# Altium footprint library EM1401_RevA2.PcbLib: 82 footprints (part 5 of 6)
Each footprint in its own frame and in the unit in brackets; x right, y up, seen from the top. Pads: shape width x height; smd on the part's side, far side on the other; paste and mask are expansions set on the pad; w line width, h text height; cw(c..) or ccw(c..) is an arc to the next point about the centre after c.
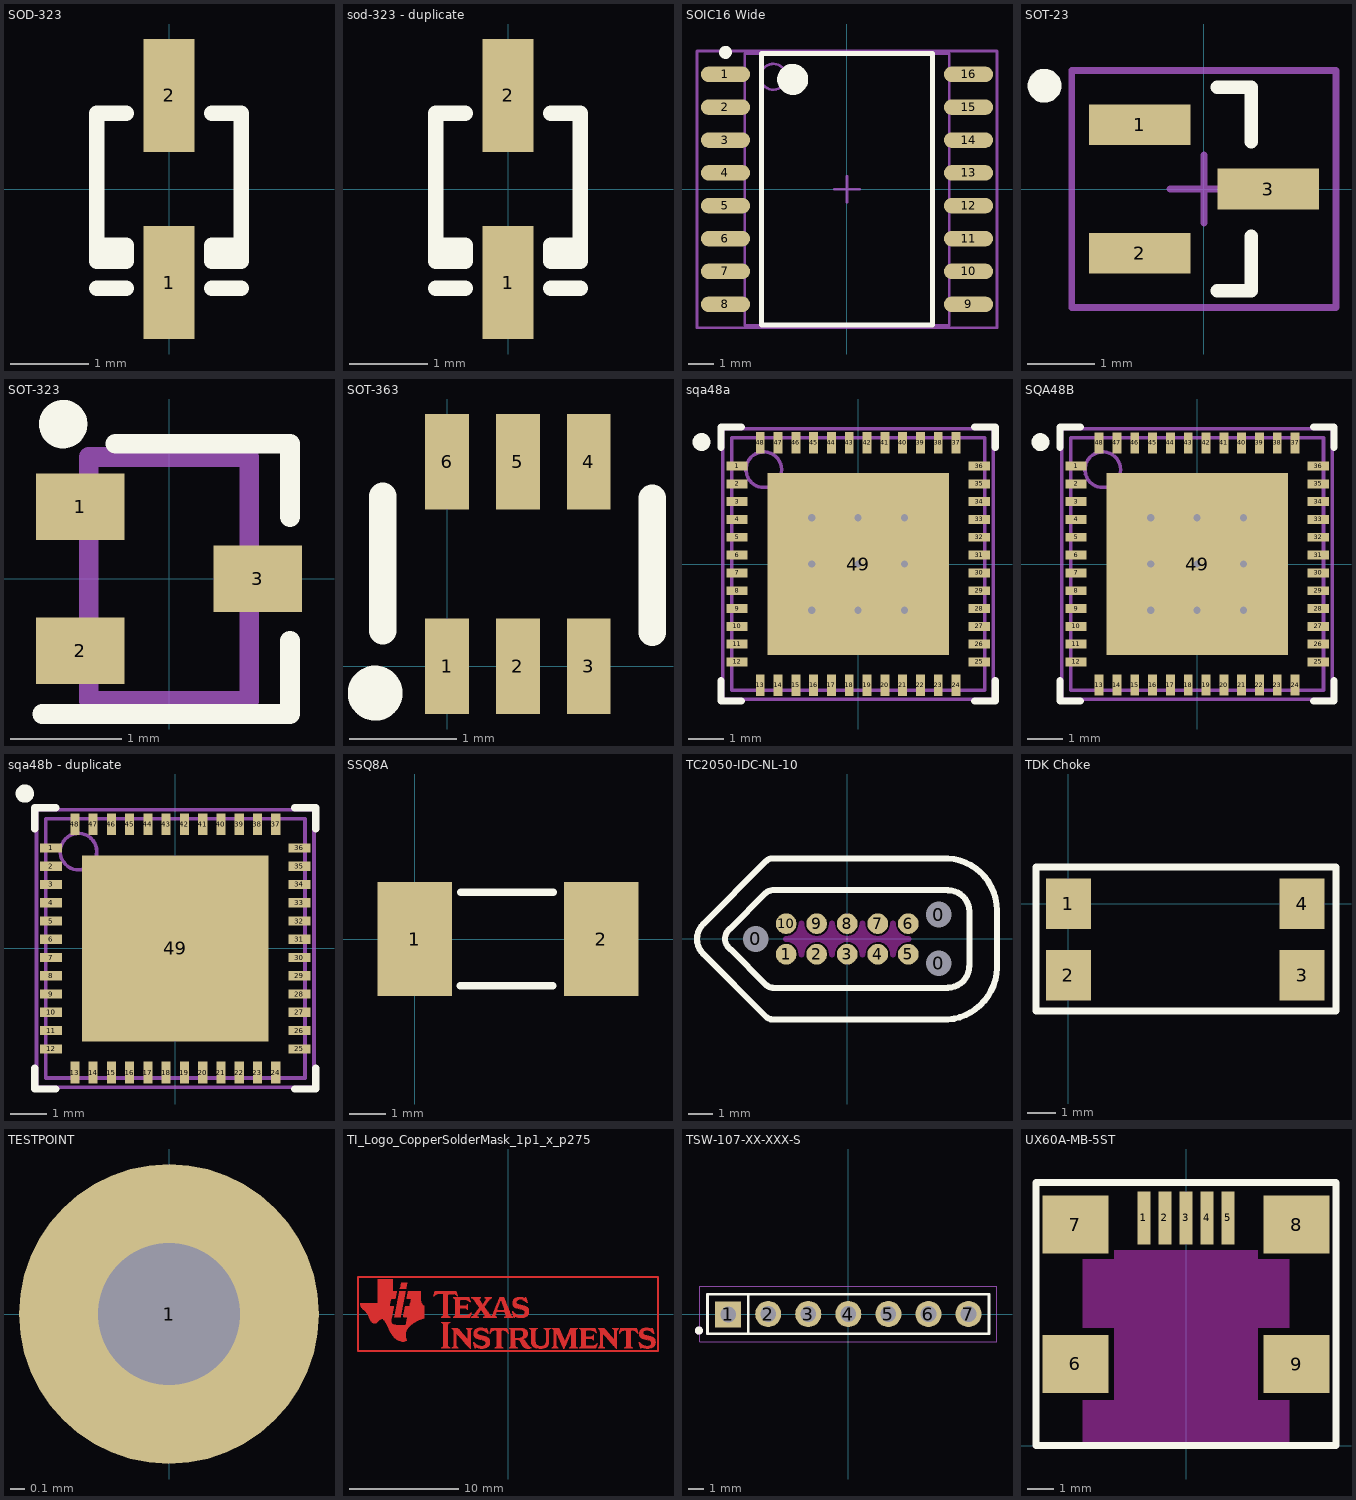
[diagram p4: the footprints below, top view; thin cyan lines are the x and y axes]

## SOD-323 [mm]
height 3.5
pads (2):
  rect 0.65x1.45 smd: 1(0,-1.2) 2(0,1.2)
Top Overlay:
  lines w0.2: -0.927,-0.725 -0.552,-0.725 -0.552,-0.926 -0.927,-0.926 -0.927,0.974 -0.552,0.974 ; -0.925,-1.275 -0.548,-1.275 ; 0.548,-1.275 0.925,-1.275 ; 0.548,0.974 0.925,0.974 0.925,-0.926 0.548,-0.926 0.548,-0.725 0.925,-0.725
Mechanical 5:
  text ".designator" at 0,-2 h1.02

## sod-323 - duplicate [mm]
pads (2):
  rect 0.65x1.45 smd: 1(0,-1.2) 2(0,1.2)
Top Overlay:
  lines w0.2: -0.927,-0.725 -0.552,-0.725 -0.552,-0.926 -0.927,-0.926 -0.927,0.974 -0.552,0.974 ; -0.925,-1.275 -0.548,-1.275 ; 0.548,-1.275 0.925,-1.275 ; 0.548,0.974 0.925,0.974 0.925,-0.926 0.548,-0.926 0.548,-0.725 0.925,-0.725
Mechanical 5:
  text ".designator" at 0,-2 h1.02

## SOIC16 Wide [mm]
pads (16):
  oval 1.9x0.6 smd: 1(-4.7,4.445) 2(-4.7,3.175) 3(-4.7,1.905) 4(-4.7,0.635) 5(-4.7,-0.635) 6(-4.7,-1.905) 7(-4.7,-3.175) 8(-4.7,-4.445) 9(4.7,-4.445) 10(4.7,-3.175) 11(4.7,-1.905) 12(4.7,-0.635) 13(4.7,0.635) 14(4.7,1.905) 15(4.7,3.175) 16(4.7,4.445)
Top Overlay:
  circle w0.6: c-2.1,4.25 r0.3
  circle w0.25: c-4.7,5.295 r0.125
  lines w0.2: -3.3,-5.25 3.3,-5.25 3.3,5.25 -3.3,5.25 -3.3,-5.25
Mechanical 5:
  text ".Designator" at -1.524,-0.508 h1.02
Mechanical 13:
  circle w0.1: c-2.85,4.35 r0.5
  lines w0.1: -3.95,-5.25 3.95,-5.25 3.95,5.25 -3.95,5.25 -3.95,-5.25
Mechanical 15:
  lines w0.1: -0.5,0 0.5,0 ; 0,-0.5 0,0.5 ; -5.8,-5.35 5.8,-5.35 5.8,5.35 -5.8,5.35 -5.8,-5.35
3D body: height 2.65, standoff 0, extent -3.95,-5.25 3.95,5.25

## SOT-23 [mm] "SOT23, 3-Leads, Body 2.9x1.3mm, Pitch 0.95mm, Lead Span 2.5mm, IPC Medium Density"
height 1.1
pads (3):
  rect 1.5x0.6 smd: 1(-0.95,0.95) 2(-0.95,-0.95) 3(0.95,0)
Top Overlay:
  circle w0.25: c-2.354,1.524 r0.125
  lines w0.2: 0.2,-1.5 0.7,-1.5 0.7,-0.7 ; 0.2,1.5 0.7,1.5 0.7,0.7
Mechanical 5:
  text ".Designator" at -1.524,-0.508 h1.02
Mechanical 15:
  lines w0.1: -0.5,0 0.5,0 ; 0,-0.5 0,0.5 ; -1.95,-1.75 -1.95,1.75 1.95,1.75 1.95,-1.75 -1.95,-1.75
3D body: height 1, standoff 0, extent -1.16,-1.45 1.21,1.45

## SOT-323 [mm] "SC-70-3 and SOT-323 footrpint"
height 1.1
pads (3):
  rect 0.8x0.6 smd: 1(-0.8,0.65) 2(-0.8,-0.65) 3(0.8,0)
Top Overlay:
  circle w0.254: c-0.955,1.397 r0.092
  lines w0.178: -1.143,-1.219 1.092,-1.219 1.092,-0.559 ; -0.483,1.219 1.092,1.219 1.092,0.559
Mechanical 5:
  text ".Designator" at -1.524,-0.508 h1.02
Mechanical 13:
  lines w0.178: -0.725,-1.1 0,-1.1 0.725,-1.1 0.725,0 0.725,1.1 0,1.1 -0.725,1.1 -0.725,0 -0.725,-1.1
3D body: height 1.1, standoff 0, extent -0.724,-1.099 0.724,1.099

## SOT-363 [mil] "SOT-363 FOOTPRINT"
height 137.8
pads (6):
  rect 16x35 smd: 1(0,0) 2(26,0) 3(52,0) 4(52,75) 5(26,75) 6(0,75)
Top Overlay:
  circle w11.81: c-26.35,-9.84 r4.16
  lines w10: -23.6,13 -23.6,62.3 ; 75.2,12.4 75.2,61.7

## sqa48a [mm] "QFN, 48-Leads, Body 7x7mm, Pitch 0.5mm, NSC Recommended"
height 0.8
pads (49):
  rect 0.6x0.25 smd paste-0.125 mask+0.051: 1(-3.4,2.75) 2(-3.4,2.25) 3(-3.4,1.75) 4(-3.4,1.25) 5(-3.4,0.75) 6(-3.4,0.25) 7(-3.4,-0.25) 8(-3.4,-0.75) 9(-3.4,-1.25) 10(-3.4,-1.75) 11(-3.4,-2.25) 12(-3.4,-2.75) 25(3.4,-2.75) 26(3.4,-2.25) 27(3.4,-1.75) 28(3.4,-1.25) 29(3.4,-0.75) 30(3.4,-0.25) 31(3.4,0.25) 32(3.4,0.75) 33(3.4,1.25) 34(3.4,1.75) 35(3.4,2.25) 36(3.4,2.75)
  rect 0.25x0.6 smd paste-0.125 mask+0.051: 13(-2.75,-3.4) 14(-2.25,-3.4) 15(-1.75,-3.4) 16(-1.25,-3.4) 17(-0.75,-3.4) 18(-0.25,-3.4) 19(0.25,-3.4) 20(0.75,-3.4) 21(1.25,-3.4) 22(1.75,-3.4) 23(2.25,-3.4) 24(2.75,-3.4) 37(2.75,3.4) 38(2.25,3.4) 39(1.75,3.4) 40(1.25,3.4) 41(0.75,3.4) 42(0.25,3.4) 43(-0.25,3.4) 44(-0.75,3.4) 45(-1.25,3.4) 46(-1.75,3.4) 47(-2.25,3.4) 48(-2.75,3.4)
  rect 5.1x5.1 smd paste-2.55 mask+0.051: 49(0,0)
via 1.3,1.3 diameter 0.635 hole 0.203
via 1.3,0 diameter 0.635 hole 0.203
via 0,1.3 diameter 0.635 hole 0.203
via 0,0 diameter 0.635 hole 0.203
via 1.3,-1.3 diameter 0.635 hole 0.203
via 0,-1.3 diameter 0.635 hole 0.203
via -1.3,1.3 diameter 0.635 hole 0.203
via -1.3,0 diameter 0.635 hole 0.203
via -1.3,-1.3 diameter 0.635 hole 0.203
Top Overlay:
  circle w0.25: c-4.4,3.425 r0.125
  lines w0.2: -3.85,-3.275 -3.85,-3.85 -3.275,-3.85 ; -3.85,3.275 -3.85,3.85 -3.275,3.85 ; 3.275,-3.85 3.85,-3.85 3.85,-3.275 ; 3.275,3.85 3.85,3.85 3.85,3.275
Top Paste:
  region: 3.9,2.875 3.2,2.875 3.2,2.625 3.9,2.625
  region: 3.9,2.375 3.2,2.375 3.2,2.125 3.9,2.125
  region: 2.625,3.9 2.625,3.2 2.875,3.2 2.875,3.9
  rectangle: 1.4,1.4 2.5,2.5
  region: 3.9,1.875 3.2,1.875 3.2,1.625 3.9,1.625
  region: 3.9,0.875 3.2,0.875 3.2,0.625 3.9,0.625
  region: 3.896,1.375 3.196,1.375 3.196,1.125 3.896,1.125
  region: 3.9,-0.125 3.2,-0.125 3.2,-0.375 3.9,-0.375
  region: 3.9,0.375 3.2,0.375 3.2,0.125 3.9,0.125
  region: 2.125,3.9 2.125,3.2 2.375,3.2 2.375,3.9
  region: 1.625,3.9 1.625,3.2 1.875,3.2 1.875,3.9
  region: 1.125,3.9 1.125,3.2 1.375,3.2 1.375,3.9
  region: 0.625,3.9 0.625,3.2 0.875,3.2 0.875,3.9
  region: 0.125,3.9 0.125,3.2 0.375,3.2 0.375,3.9
  region: -0.375,3.9 -0.375,3.2 -0.125,3.2 -0.125,3.9
  rectangle: 1.4,0.1 2.5,1.2
  rectangle: 0.1,1.4 1.2,2.5
  rectangle: 0.1,0.1 1.2,1.2
  region: 3.9,-0.625 3.2,-0.625 3.2,-0.875 3.9,-0.875
  region: 3.896,-1.125 3.196,-1.125 3.196,-1.375 3.896,-1.375
  region: 1.4,-0.1 1.4,-1.2 2.5,-1.2 2.5,-0.1
  region: 3.9,-1.625 3.2,-1.625 3.2,-1.875 3.9,-1.875
  region: 3.9,-2.125 3.2,-2.125 3.2,-2.375 3.9,-2.375
  region: 3.9,-2.625 3.2,-2.625 3.2,-2.875 3.9,-2.875
  region: 2.875,-3.9 2.875,-3.2 2.625,-3.2 2.625,-3.9
  region: 1.4,-1.4 1.4,-2.5 2.5,-2.5 2.5,-1.4
  region: 0.1,-0.1 0.1,-1.2 1.2,-1.2 1.2,-0.1
  region: 0.1,-1.4 0.1,-2.5 1.2,-2.5 1.2,-1.4
  region: 1.371,-3.9 1.371,-3.2 1.121,-3.2 1.121,-3.9
  region: 0.871,-3.9 0.871,-3.2 0.621,-3.2 0.621,-3.9
  region: 2.375,-3.9 2.375,-3.2 2.125,-3.2 2.125,-3.9
  region: 1.875,-3.9 1.875,-3.2 1.625,-3.2 1.625,-3.9
  region: 0.375,-3.9 0.375,-3.2 0.125,-3.2 0.125,-3.9
  region: -0.125,-3.9 -0.125,-3.2 -0.375,-3.2 -0.375,-3.9
  region: -0.875,3.9 -0.875,3.2 -0.625,3.2 -0.625,3.9
  region: -1.375,3.9 -1.375,3.2 -1.125,3.2 -1.125,3.9
  region: -1.875,3.9 -1.875,3.2 -1.625,3.2 -1.625,3.9
  region: -0.1,2.5 -1.2,2.5 -1.2,1.4 -0.1,1.4
  region: -0.1,1.2 -1.2,1.2 -1.2,0.1 -0.1,0.1
  region: -1.4,1.2 -2.5,1.2 -2.5,0.1 -1.4,0.1
  region: -1.4,2.5 -2.5,2.5 -2.5,1.4 -1.4,1.4
  region: -2.375,3.9 -2.375,3.2 -2.125,3.2 -2.125,3.9
  region: -2.875,3.9 -2.875,3.2 -2.625,3.2 -2.625,3.9
  rectangle: -3.9,2.625 -3.2,2.875
  rectangle: -3.9,1.625 -3.2,1.875
  rectangle: -3.9,1.125 -3.2,1.375
  rectangle: -3.9,2.125 -3.2,2.375
  rectangle: -3.9,0.125 -3.2,0.375
  rectangle: -3.9,0.625 -3.2,0.875
  region: -1.2,-0.1 -1.2,-1.2 -0.1,-1.2 -0.1,-0.1
  region: -1.2,-1.4 -1.2,-2.5 -0.1,-2.5 -0.1,-1.4
  region: -2.5,-1.4 -2.5,-2.5 -1.4,-2.5 -1.4,-1.4
  region: -2.5,-0.1 -2.5,-1.2 -1.4,-1.2 -1.4,-0.1
  region: -1.129,-3.9 -1.129,-3.2 -1.379,-3.2 -1.379,-3.9
  region: -0.625,-3.9 -0.625,-3.2 -0.875,-3.2 -0.875,-3.9
  region: -1.629,-3.9 -1.629,-3.2 -1.879,-3.2 -1.879,-3.9
  region: -2.125,-3.9 -2.125,-3.2 -2.375,-3.2 -2.375,-3.9
  rectangle: -3.9,-0.875 -3.2,-0.625
  rectangle: -3.9,-0.375 -3.2,-0.125
  rectangle: -3.9,-1.375 -3.2,-1.125
  rectangle: -3.9,-2.375 -3.2,-2.125
  region: -2.625,-3.9 -2.625,-3.2 -2.875,-3.2 -2.875,-3.9
  rectangle: -3.9,-2.875 -3.2,-2.625
  rectangle: -3.9,-1.875 -3.2,-1.625
Mechanical 13:
  circle w0.1: c-2.65,2.65 r0.5
  lines w0.1: -3.55,-3.55 3.55,-3.55 3.55,3.55 -3.55,3.55 -3.55,-3.55
Mechanical 15:
  lines w0.1: -0.5,0 0.5,0 ; 0,-0.5 0,0.5 ; -3.8,-3.8 3.8,-3.8 3.8,3.8 -3.8,3.8 -3.8,-3.8
3D body: height 0.8, standoff 0, extent -3.55,-3.55 3.55,3.55

## SQA48B [mm] "QFN, 48-Leads, Body 7x7mm, Pitch 0.5mm, NSC Recommended"
height 0.8
pads (49):
  rect 0.6x0.25 smd paste-0.125 mask+0.051: 1(-3.4,2.75) 2(-3.4,2.25) 3(-3.4,1.75) 4(-3.4,1.25) 5(-3.4,0.75) 6(-3.4,0.25) 7(-3.4,-0.25) 8(-3.4,-0.75) 9(-3.4,-1.25) 10(-3.4,-1.75) 11(-3.4,-2.25) 12(-3.4,-2.75) 25(3.4,-2.75) 26(3.4,-2.25) 27(3.4,-1.75) 28(3.4,-1.25) 29(3.4,-0.75) 30(3.4,-0.25) 31(3.4,0.25) 32(3.4,0.75) 33(3.4,1.25) 34(3.4,1.75) 35(3.4,2.25) 36(3.4,2.75)
  rect 0.25x0.6 smd paste-0.125 mask+0.051: 13(-2.75,-3.4) 14(-2.25,-3.4) 15(-1.75,-3.4) 16(-1.25,-3.4) 17(-0.75,-3.4) 18(-0.25,-3.4) 19(0.25,-3.4) 20(0.75,-3.4) 21(1.25,-3.4) 22(1.75,-3.4) 23(2.25,-3.4) 24(2.75,-3.4) 37(2.75,3.4) 38(2.25,3.4) 39(1.75,3.4) 40(1.25,3.4) 41(0.75,3.4) 42(0.25,3.4) 43(-0.25,3.4) 44(-0.75,3.4) 45(-1.25,3.4) 46(-1.75,3.4) 47(-2.25,3.4) 48(-2.75,3.4)
  rect 5.1x5.1 smd paste-2.55 mask+0.051: 49(0,0)
via -1.3,1.3 diameter 0.635 hole 0.203
via 0,0 diameter 0.635 hole 0.203
via 0,1.3 diameter 0.635 hole 0.203
via 1.3,1.3 diameter 0.635 hole 0.203
via 1.3,0 diameter 0.635 hole 0.203
via -1.3,0 diameter 0.635 hole 0.203
via -1.3,-1.3 diameter 0.635 hole 0.203
via 0,-1.3 diameter 0.635 hole 0.203
via 1.3,-1.3 diameter 0.635 hole 0.203
Top Overlay:
  circle w0.25: c-4.4,3.425 r0.125
  lines w0.2: -3.85,-3.275 -3.85,-3.85 -3.275,-3.85 ; -3.85,3.275 -3.85,3.85 -3.275,3.85 ; 3.275,-3.85 3.85,-3.85 3.85,-3.275 ; 3.275,3.85 3.85,3.85 3.85,3.275
Top Paste:
  region: -2.377,3.9 -2.377,3.2 -2.127,3.2 -2.127,3.9
  region: -2.877,3.9 -2.877,3.2 -2.627,3.2 -2.627,3.9
  region: -1.877,3.9 -1.877,3.2 -1.627,3.2 -1.627,3.9
  region: -0.875,3.901 -0.875,3.201 -0.625,3.201 -0.625,3.901
  region: -1.375,3.898 -1.375,3.198 -1.125,3.198 -1.125,3.898
  region: 0.123,3.9 0.123,3.2 0.373,3.2 0.373,3.9
  region: -0.377,3.9 -0.377,3.2 -0.127,3.2 -0.127,3.9
  rectangle: -3.902,2.125 -3.202,2.375
  rectangle: -3.902,2.625 -3.202,2.875
  rectangle: -3.9,1.623 -3.2,1.873
  rectangle: -3.902,0.125 -3.202,0.375
  rectangle: -3.902,-0.375 -3.202,-0.125
  rectangle: -3.9,1.123 -3.2,1.373
  rectangle: -3.902,0.625 -3.202,0.875
  region: -1.4,2.5 -2.5,2.5 -2.5,1.4 -1.4,1.4
  region: -0.1,2.5 -1.2,2.5 -1.2,1.4 -0.1,1.4
  region: -1.4,1.2 -2.5,1.2 -2.5,0.1 -1.4,0.1
  region: -0.1,1.2 -1.2,1.2 -1.2,0.1 -0.1,0.1
  region: 0.623,3.9 0.623,3.2 0.873,3.2 0.873,3.9
  region: 1.125,3.898 1.125,3.198 1.375,3.198 1.375,3.898
  rectangle: 1.4,1.4 2.5,2.5
  region: 2.123,3.9 2.123,3.2 2.373,3.2 2.373,3.9
  region: 2.623,3.9 2.623,3.2 2.873,3.2 2.873,3.9
  region: 1.625,3.898 1.625,3.198 1.875,3.198 1.875,3.898
  region: 3.898,2.875 3.198,2.875 3.198,2.625 3.898,2.625
  rectangle: 0.1,1.4 1.2,2.5
  rectangle: 0.1,0.1 1.2,1.2
  rectangle: 1.4,0.1 2.5,1.2
  region: 3.898,2.375 3.198,2.375 3.198,2.125 3.898,2.125
  region: 3.898,1.875 3.198,1.875 3.198,1.625 3.898,1.625
  region: 3.901,1.372 3.201,1.372 3.201,1.122 3.901,1.122
  region: 3.9,0.875 3.2,0.875 3.2,0.625 3.9,0.625
  region: 3.898,0.375 3.198,0.375 3.198,0.125 3.898,0.125
  region: 3.898,-0.125 3.198,-0.125 3.198,-0.375 3.898,-0.375
  rectangle: -3.9,-0.877 -3.2,-0.627
  rectangle: -3.9,-1.377 -3.2,-1.127
  rectangle: -3.902,-1.875 -3.202,-1.625
  region: -2.5,-0.1 -2.5,-1.2 -1.4,-1.2 -1.4,-0.1
  region: -1.2,-0.1 -1.2,-1.2 -0.1,-1.2 -0.1,-0.1
  region: -2.5,-1.4 -2.5,-2.5 -1.4,-2.5 -1.4,-1.4
  region: -1.2,-1.4 -1.2,-2.5 -0.1,-2.5 -0.1,-1.4
  rectangle: -3.902,-2.375 -3.202,-2.125
  rectangle: -3.902,-2.875 -3.202,-2.625
  region: -2.127,-3.9 -2.127,-3.2 -2.377,-3.2 -2.377,-3.9
  region: -2.627,-3.9 -2.627,-3.2 -2.877,-3.2 -2.877,-3.9
  region: -0.127,-3.9 -0.127,-3.2 -0.377,-3.2 -0.377,-3.9
  region: -1.123,-3.903 -1.123,-3.203 -1.373,-3.203 -1.373,-3.903
  region: -1.623,-3.903 -1.623,-3.203 -1.873,-3.203 -1.873,-3.903
  region: 0.373,-3.9 0.373,-3.2 0.123,-3.2 0.123,-3.9
  region: -0.627,-3.9 -0.627,-3.2 -0.877,-3.2 -0.877,-3.9
  region: 0.1,-0.1 0.1,-1.2 1.2,-1.2 1.2,-0.1
  region: 1.4,-0.1 1.4,-1.2 2.5,-1.2 2.5,-0.1
  region: 1.4,-1.4 1.4,-2.5 2.5,-2.5 2.5,-1.4
  region: 0.1,-1.4 0.1,-2.5 1.2,-2.5 1.2,-1.4
  region: 3.898,-0.625 3.198,-0.625 3.198,-0.875 3.898,-0.875
  region: 3.901,-1.128 3.201,-1.128 3.201,-1.378 3.901,-1.378
  region: 3.9,-1.625 3.2,-1.625 3.2,-1.875 3.9,-1.875
  region: 3.898,-2.125 3.198,-2.125 3.198,-2.375 3.898,-2.375
  region: 1.376,-3.903 1.376,-3.203 1.126,-3.203 1.126,-3.903
  region: 0.876,-3.903 0.876,-3.203 0.626,-3.203 0.626,-3.903
  region: 1.873,-3.9 1.873,-3.2 1.623,-3.2 1.623,-3.9
  region: 3.898,-2.625 3.198,-2.625 3.198,-2.875 3.898,-2.875
  region: 2.873,-3.9 2.873,-3.2 2.623,-3.2 2.623,-3.9
  region: 2.373,-3.9 2.373,-3.2 2.123,-3.2 2.123,-3.9
Mechanical 13:
  circle w0.1: c-2.65,2.65 r0.5
  lines w0.1: -3.55,-3.55 -3.55,3.55 3.55,3.55 3.55,-3.55 -3.55,-3.55
Mechanical 15:
  lines w0.1: -0.5,0 0.5,0 ; 0,-0.5 0,0.5 ; -3.8,-3.8 -3.8,3.8 3.8,3.8 3.8,-3.8 -3.8,-3.8
3D body: height 0.8, standoff 0, extent -3.55,-3.55 3.55,3.55

## sqa48b - duplicate [mm]
pads (49):
  rect 0.6x0.25 smd paste-0.125 mask+0.051: 1(-3.4,2.75) 2(-3.4,2.25) 3(-3.4,1.75) 4(-3.4,1.25) 5(-3.4,0.75) 6(-3.4,0.25) 7(-3.4,-0.25) 8(-3.4,-0.75) 9(-3.4,-1.25) 10(-3.4,-1.75) 11(-3.4,-2.25) 12(-3.4,-2.75) 25(3.4,-2.75) 26(3.4,-2.25) 27(3.4,-1.75) 28(3.4,-1.25) 29(3.4,-0.75) 30(3.4,-0.25) 31(3.4,0.25) 32(3.4,0.75) 33(3.4,1.25) 34(3.4,1.75) 35(3.4,2.25) 36(3.4,2.75)
  rect 0.25x0.6 smd paste-0.125 mask+0.051: 13(-2.75,-3.4) 14(-2.25,-3.4) 15(-1.75,-3.4) 16(-1.25,-3.4) 17(-0.75,-3.4) 18(-0.25,-3.4) 19(0.25,-3.4) 20(0.75,-3.4) 21(1.25,-3.4) 22(1.75,-3.4) 23(2.25,-3.4) 24(2.75,-3.4) 37(2.75,3.4) 38(2.25,3.4) 39(1.75,3.4) 40(1.25,3.4) 41(0.75,3.4) 42(0.25,3.4) 43(-0.25,3.4) 44(-0.75,3.4) 45(-1.25,3.4) 46(-1.75,3.4) 47(-2.25,3.4) 48(-2.75,3.4)
  rect 5.1x5.1 smd paste-2.55 mask+0.051: 49(0,0)
Top Overlay:
  circle w0.25: c-4.12,4.24 r0.125
  lines w0.2: -3.85,-3.275 -3.85,-3.85 -3.275,-3.85 ; -3.85,3.275 -3.85,3.85 -3.275,3.85 ; 3.275,-3.85 3.85,-3.85 3.85,-3.275 ; 3.275,3.85 3.85,3.85 3.85,3.275
Top Paste:
  region: 3.898,-2.625 3.198,-2.625 3.198,-2.875 3.898,-2.875
  region: 3.9,-1.625 3.2,-1.625 3.2,-1.875 3.9,-1.875
  region: 3.898,-2.125 3.198,-2.125 3.198,-2.375 3.898,-2.375
  region: 3.9,-1.125 3.2,-1.125 3.2,-1.375 3.9,-1.375
  region: 3.898,-0.625 3.198,-0.625 3.198,-0.875 3.898,-0.875
  region: 3.898,0.375 3.198,0.375 3.198,0.125 3.898,0.125
  region: 3.898,-0.125 3.198,-0.125 3.198,-0.375 3.898,-0.375
  region: 2.374,-3.9 2.374,-3.2 2.124,-3.2 2.124,-3.9
  region: 2.874,-3.9 2.874,-3.2 2.624,-3.2 2.624,-3.9
  region: 1.874,-3.9 1.874,-3.2 1.624,-3.2 1.624,-3.9
  region: 1.375,-3.9 1.375,-3.2 1.125,-3.2 1.125,-3.9
  region: 0.875,-3.9 0.875,-3.2 0.625,-3.2 0.625,-3.9
  region: 0.374,-3.9 0.374,-3.2 0.124,-3.2 0.124,-3.9
  region: -0.126,-3.9 -0.126,-3.2 -0.376,-3.2 -0.376,-3.9
  region: 1.4,-0.1 1.4,-1.2 2.5,-1.2 2.5,-0.1
  region: 1.4,-1.4 1.4,-2.5 2.5,-2.5 2.5,-1.4
  region: 0.1,-0.1 0.1,-1.2 1.2,-1.2 1.2,-0.1
  region: 0.1,-1.4 0.1,-2.5 1.2,-2.5 1.2,-1.4
  region: 3.9,0.875 3.2,0.875 3.2,0.625 3.9,0.625
  region: 3.9,1.375 3.2,1.375 3.2,1.125 3.9,1.125
  region: 3.898,1.875 3.198,1.875 3.198,1.625 3.898,1.625
  rectangle: 1.4,0.1 2.5,1.2
  region: 3.898,2.875 3.198,2.875 3.198,2.625 3.898,2.625
  region: 3.898,2.375 3.198,2.375 3.198,2.125 3.898,2.125
  region: 2.623,3.9 2.623,3.2 2.873,3.2 2.873,3.9
  rectangle: 1.4,1.4 2.5,2.5
  rectangle: 0.1,0.1 1.2,1.2
  rectangle: 0.1,1.4 1.2,2.5
  region: 2.123,3.9 2.123,3.2 2.373,3.2 2.373,3.9
  region: 1.624,3.901 1.624,3.201 1.874,3.201 1.874,3.901
  region: 1.124,3.901 1.124,3.201 1.374,3.201 1.374,3.901
  region: 0.624,3.9 0.624,3.2 0.874,3.2 0.874,3.9
  region: 0.124,3.9 0.124,3.2 0.374,3.2 0.374,3.9
  region: -0.376,3.9 -0.376,3.2 -0.126,3.2 -0.126,3.9
  region: -1.125,-3.9 -1.125,-3.2 -1.375,-3.2 -1.375,-3.9
  region: -0.626,-3.9 -0.626,-3.2 -0.876,-3.2 -0.876,-3.9
  region: -1.625,-3.9 -1.625,-3.2 -1.875,-3.2 -1.875,-3.9
  region: -2.626,-3.9 -2.626,-3.2 -2.876,-3.2 -2.876,-3.9
  region: -2.126,-3.9 -2.126,-3.2 -2.376,-3.2 -2.376,-3.9
  region: -1.2,-1.4 -1.2,-2.5 -0.1,-2.5 -0.1,-1.4
  region: -1.2,-0.1 -1.2,-1.2 -0.1,-1.2 -0.1,-0.1
  region: -2.5,-0.1 -2.5,-1.2 -1.4,-1.2 -1.4,-0.1
  region: -2.5,-1.4 -2.5,-2.5 -1.4,-2.5 -1.4,-1.4
  rectangle: -3.901,-2.375 -3.201,-2.125
  rectangle: -3.901,-1.875 -3.201,-1.625
  rectangle: -3.901,-2.875 -3.201,-2.625
  rectangle: -3.9,-0.874 -3.2,-0.624
  rectangle: -3.9,-1.374 -3.2,-1.124
  rectangle: -3.901,-0.375 -3.201,-0.125
  rectangle: -3.901,0.625 -3.201,0.875
  rectangle: -3.901,0.125 -3.201,0.375
  region: -0.1,1.2 -1.2,1.2 -1.2,0.1 -0.1,0.1
  region: -0.1,2.5 -1.2,2.5 -1.2,1.4 -0.1,1.4
  region: -1.4,1.2 -2.5,1.2 -2.5,0.1 -1.4,0.1
  region: -1.4,2.5 -2.5,2.5 -2.5,1.4 -1.4,1.4
  region: -0.875,3.898 -0.875,3.198 -0.625,3.198 -0.625,3.898
  region: -1.375,3.901 -1.375,3.201 -1.125,3.201 -1.125,3.901
  region: -1.876,3.9 -1.876,3.2 -1.626,3.2 -1.626,3.9
  region: -2.376,3.9 -2.376,3.2 -2.126,3.2 -2.126,3.9
  rectangle: -3.9,1.626 -3.2,1.876
  rectangle: -3.9,1.126 -3.2,1.376
  rectangle: -3.901,2.625 -3.201,2.875
  region: -2.876,3.9 -2.876,3.2 -2.626,3.2 -2.626,3.9
  rectangle: -3.901,2.125 -3.201,2.375
Mechanical 13:
  circle w0.1: c-2.65,2.65 r0.5
  lines w0.1: -3.55,-3.55 3.55,-3.55 3.55,3.55 -3.55,3.55 -3.55,-3.55
Mechanical 15:
  lines w0.1: -0.5,0 0.5,0 ; 0,-0.5 0,0.5 ; -3.8,-3.8 3.8,-3.8 3.8,3.8 -3.8,3.8 -3.8,-3.8
3D body: height 0.8, standoff 0, extent -3.55,-3.55 3.55,3.55

## SSQ8A [mm] "Bel Fuse SMT Quick Acting Fuse"
height 2.54
pads (2):
  rect 2.032x3.1 smd: 1(0,0) 2(5.08,0)
Top Overlay:
  lines w0.203: 1.24,-1.27 3.765,-1.27 ; 1.25,1.27 3.775,1.27
Mechanical 5:
  text ".designator" at 1.495,-0.42 h1.02
3D body: height 2.54, standoff 0, extent 0,-1.27 5.08,1.27

## TC2050-IDC-NL-10 [mil]
pads (13):
  round 39 hole 42 unplated: 0(-150,0) 0(150,-40) 0(150,40)
  round 34 smd: 1(-100,-25) 2(-50,-25) 3(0,-25) 4(50,-25) 5(100,-25) 6(100,25) 7(50,25) 8(0,25) 9(-50,25) 10(-100,25)
Top Overlay:
  lines w10: -236.02,24.32 -132.42,127.92 cw(c-120.91,113.83) -120,132 165,132 cw(c160,47) 245.15,47 ; -235.97,-24.19 -132.37,-127.78 ccw(c-120.71,-113.82) -120,-132 165,-132 ccw(c158,-45) 245.25,-47.35 ; -235.6,-24.55 cw(c-211.74,0.03) -235.57,24.65 ; -133.15,75.43 -191.54,17.04 ccw(c-178.99,0.19) -190.97,-17.07 -132.58,-75.46 ; -132.42,75.92 cw(c-120.91,61.83) -120,80 165.34,80 ; -132.37,-75.78 ccw(c-120.71,-61.82) -120,-80 165,-80 ; 165,-79.66 ccw(c165,-45) 199.66,-45 ; 165.34,79.66 cw(c165.34,45) 200,45 200,-45 ; 245,-47.34 245,45
Keep-Out Layer:
  region: -6.61,0 -25,18.38 -43.38,0 -25,-18.38
  region: -56.61,0 -75,18.38 -93.38,0 -75,-18.38
  region: 43.39,0 25,18.38 6.62,0 25,-18.38
  region: 93.39,0 75,18.38 56.62,0 75,-18.38
  lines w10: -100,-0.02 ccw(c-100,25) -74.98,25 ; -100,0.08 cw(c-100,-25) -74.92,-25 cw(c-50,-25) -50,-0.08 ; -75.08,25 ccw(c-50,25) -50,-0.08 ; -50,0.02 cw(c-50,-25) -24.98,-25 ; -25.08,-25 cw(c0,-25) 0,0.08 ; 50,-0.02 ccw(c50,25) 75.02,25 ; 50,0.18 cw(c50,-25) 75.18,-25 cw(c100,-25) 100,-0.18 cw(c100,25) 74.82,25 ; -50,-0.08 ccw(c-50,25) -24.92,25 ccw(c0,25) 0,0.08 ; 0,0.08 cw(c0,-25) 25.08,-25 cw(c50,-25) 50,-0.08 cw(c50,25) 24.92,25 cw(c0,25) 0,0.08

## TDK Choke [mm]
pads (4):
  rect 1.6x1.8 smd: 1(0,0) 2(0,-2.54) 3(8.3,-2.54) 4(8.3,0)
Top Overlay:
  lines w0.254: -1.15,-3.8 -1.15,1.3 9.5,1.3 9.5,-3.8 -1.15,-3.8

## TESTPOINT [mil]
height 314.96
pads (1):
  round 80 hole 37.99: 1(0,0)

## TI_Logo_CopperSolderMask_1p1_x_p275 [mm]
Top Layer:
  drawing of 22 lines, arcs and shapes, not listed
Top Solder:
  drawing of 18 lines, arcs and shapes, not listed

## TSW-107-XX-XXX-S [mm] "2.54mm pitch, 7 pin, terminal strip; straight, single row"
height 2.54
pads (7):
  rect 1.65x1.65 hole 1 mask+0: 1(-7.62,-0.025)
  round 1.65 hole 1 mask+0: 2(-5.08,0) 3(-2.54,0) 4(0,0) 5(2.54,0) 6(5.08,0) 7(7.62,0)
Top Overlay:
  circle w0.25: c-9.47,-1.05 r0.125
  lines w0.178: -6.35,-1.25 -6.35,1.25 ; -8.92,-1.25 -8.92,1.25 8.93,1.25 8.93,-1.25 -8.92,-1.25
Mechanical 5:
  text ".Designator" at -1.524,-0.508 h1.52
Mechanical 13:
  circle w0.25: c-9.47,-1.05 r0.125
  lines w0.1: -8.92,-1.25 -8.92,1.25 8.93,1.25 8.93,-1.25 -8.92,-1.25
Mechanical 15:
  lines w0.05: -9.42,-1.75 -9.42,1.75 9.43,1.75 9.43,-1.75 -9.42,-1.75
3D body: height 8.38, standoff -2.54, extent -8.89,-1.27 8.89,1.27

## UX60A-MB-5ST [mm] "USB mini-B Right Angle without positioning post"
height 0.1
pads (9):
  rect 0.5x2 smd: 1(-1.6,8.65) 2(-0.8,8.65) 3(0,8.65) 4(0.8,8.65) 5(1.6,8.65)
  rect 2.5x2.2 smd: 6(-4.2,3.1) 7(-4.2,8.4) 8(4.2,8.4) 9(4.2,3.1)
Top Overlay:
  lines w0.254: -5.7,0 -5.7,10 5.7,10 5.7,0 -5.7,0
Keep-Out Layer:
  region: -3.925,0 3.925,0 3.925,1.725 2.725,1.725 2.725,4.475 3.925,4.475 3.925,7.075 2.725,7.075 2.725,7.425 -2.725,7.425 -2.725,7.075 -3.925,7.075 -3.925,4.475 -2.725,4.475 -2.725,1.725 -3.925,1.725
3D body: height 3.95, standoff 0, extent -5,0 5,10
